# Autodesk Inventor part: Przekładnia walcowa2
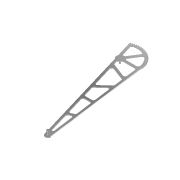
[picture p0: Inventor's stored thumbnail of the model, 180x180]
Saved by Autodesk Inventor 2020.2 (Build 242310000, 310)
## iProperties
Manager: www.cadconsulting.pl
Company: Fabian Stasiak CAD Consulting
CustomPartVersion: 1
Created: 2014-10
Part Number: Przekładnia walcowa2
Material: Steel
Document SubType Name: Modeling
Designer: F.Stasiak
Categories: <?xml version="1.0" encoding="UTF-16"?> <MemberInstance><Categories><FamilyTemplate><FamilyTemplateParameter ValueType="xs:double" Id="1" ObjectReferenceKey="da
Density: 7.85 g/cm^3
Appearance: Chrom - polerowany
Mass: 1025.76 g
Surface Area: 707.949 cm^2
Volume: 130.67 cm^3
Catalog Web Link: www.expertbooks.pl
Author: F.Stasiak
Subject: Zbiór ćwiczeń. Autodesk Inventor 2020. Kurs Professional
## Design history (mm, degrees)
sketch "Sketch1"
  geometry: C1 r 112.125 at (0, 0)
  constraints: 1 centre point
  dimensions: "d0" = 224.25 diameter of C1 (= da_da)
extrude "Extrusion1" new body sketch "Sketch1" distance "d1" = 5 (= da_b); taper "d2" = 0 deg
workplane "Work Plane2"
sketch "Sketch2"
  geometry: C1 r 112.125 at (0, 0) reference; C2 r 109.255 at (0, 0)
  constraints: 1 centre point, 1 coincident
  dimensions: "d3" = 218.51064 diameter of C2 (= da_dw)
feature "Średnica podziałowa" sketch "Sketch2" dims "d4" = 10, "d5" = 0
workplane "Work Plane8"
workplane "Work Plane9"
feature "Przekładnia walcowa" dims "da_b" = 5, "da_d" = 217.25, "da_aw" = 130, "da_da" = 224.25, "da_df" = 211.9072, "da_dw" = 218.51064, angle "da_beta" = 0 deg, "da_lefttooth" = 0, "da_righttooth" = 0
sketch "Szkic8"
  geometry: C1 r 8 at (0, 0); 1 further point
  constraints: 1 centre point, 1 coincident
  dimensions: "d66" = 16 diameter of C1
extrude "Wyciągnięcie proste6" join sketch "Szkic8" distance "d67" = 2; taper "d68" = 0 deg
sketch "Szkic9"
  geometry: C1 r 4 at (0, 0); 1 further point
  constraints: 1 centre point, 1 coincident
  dimensions: "d69" = 8 diameter of C1
extrude "Wyciągnięcie proste7" join sketch "Szkic9" distance "d70" = 20; taper "d71" = 0 deg
sketch "Szkic10"
  geometry: C1 r 8 at (0, 0); 1 further point
  constraints: 1 centre point, 1 coincident
  dimensions: "d72" = 16 diameter of C1
extrude "Wyciągnięcie proste8" join sketch "Szkic10" distance "d73" = 2; taper "d74" = 0 deg
sketch "Szkic11"
  geometry: L1 (125, 0)-(15, 0); L2 (-6.339, 13.595)-(-52.827, 113.288); L3 (15, 0)-(0, 0); L4 (0, 0)-(-6.339, 13.595); A1 r 125 centre (0, 0) between (-52.827, 113.288) and (125, 0); A2 r 15 centre (0, 0) between (-6.339, 13.595) and (15, 0); 1 further point
  constraints: 8 end point, 4 point on circle, 2 centre point, 2 coincident, 2 horizontal, 1 collinear
  dimensions: "d75" = 250 diameter of A1; "d76" = 115 deg angle of L2 L1; "d77" = 30 diameter of A2
extrude "Wyciągnięcie proste9" cut sketch "Szkic11" extent not by distance; stored distance "d80" = 2; taper "d81" = 0 deg
sketch "Szkic12"
  geometry: L1 (15, 0)-(109.382, 0) reference; L2 (-44.778, 96.027)-(-6.339, 13.595) reference; L3 (109, 4.23)-(185.868, -572.965); L4 (156.622, -579.222)-(-14.378, -4.276); L5 (-44.778, 96.027)-(-14.378, -4.276); L6 (109, 4.23)-(-44.778, 96.027); A1 r 6 centre (170.999, -574.946) between (165.029, -575.537) and (176.97, -574.354); A2 r 15 centre (170.999, -574.946) between (185.868, -572.965) and (156.622, -579.222); A3 r 36.765 centre (95.445, 38.404) between (105.906, 3.16) and (111.987, 5.571) reference; A4 r 15 centre (0, 0) between (-6.339, 13.595) and (15, 0) reference; A5 r 105.954 centre (0, 0) between (105.948, 1.053) and (105.906, 3.16) reference; 1 further point
  constraints: 8 end point, 6 point on circle, 3 tangent, 2 centre point, 1 coincident
  dimensions: "d82" = 30 diameter of A2
extrude "Wyciągnięcie proste10" join sketch "Szkic12" distance "d83" = 5; taper "d84" = 0 deg
sketch "Szkic13"
  geometry: C1 r 6 at (170.999, -574.946); A1 r 15 centre (170.999, -574.946) between (156.622, -579.222) and (185.868, -572.965) reference; 1 further point
  constraints: 1 centre point, 1 coincident
  dimensions: "d85" = 12 diameter of C1
extrude "Wyciągnięcie proste11" join sketch "Szkic13" distance "d86" = 25; taper "d87" = 0 deg
sketch "Szkic14"
  geometry: L1 (-14.378, -4.276)-(156.622, -579.222) reference; L2 (185.868, -572.965)-(109, 4.23) reference; L3 (122.376, -421.985)-(151.909, -408.868); L4 (150.258, -396.471)-(118.927, -410.387); L5 (136.695, -294.632)-(84.499, -294.632); L6 (135.097, -282.632)-(80.93, -282.632); L7 (119.47, -165.286)-(61.685, -217.925); L8 (117.542, -150.809)-(57.886, -205.153); L9 (110.37, -96.96)-(14.913, -60.666); L10 (10.608, -46.191)-(108.569, -83.437); L11 (56.231, 78.553)-(15.206, 12.991); L12 (46.058, 84.918)-(5.042, 19.371); L13 (-4.465, 4.488)-(-5.327, 3.111); L14 (51.244, 81.894)-(10.608, 16.955); L15 (19.096, -6.001)-(98.257, -6.001); L16 (19.079, 5.999)-(96.659, 5.999); L17 (0, 0)-(4, 0); L18 (20, 0)-(97.458, 0); L19 (-30.402, 91.696)-(-8.517, 18.114); L20 (-4.465, 4.488)-(-2.121, -3.391); A1 r 96.605 centre (0, 0) between (95.759, 12.753) and (-30.402, 91.696); A2 r 6 centre (162.981, -537.462) between (157.23, -539.173) and (168.929, -536.67); A3 r 4 centre (0, 0) between (4, 0) and (-2.121, -3.391) reference; A4 r 20 centre (0, 0) between (19.079, 5.999) and (15.206, 12.991); A5 r 20.017 centre (0, 0) between (5.042, 19.371) and (19.096, -6.001); 3 further points
  constraints: 36 end point, 15 point on circle, 13 parallel, 4 centre point, 3 horizontal, 2 tangent, 1 coincident, 1 concentric, 30 other
  dimensions: "d93" = 12 dimension on L2 (= d92); "d94" = 6 radius of A2; "d96" = 12 distance between parallel lines of L4 L3 (= d92); "d97" = 12 distance between parallel lines of L6 L5 (= d92); "d98" = 12 distance between parallel lines of L8 L7 (= d92); "d99" = 12 distance between parallel lines of L10 L9 (= d92); "d102" = 12 distance between parallel lines of L12 L11; "d104" = 12 distance between parallel lines of L16 L15; "d113" = 12 dimension on L1
extrude "Wyciągnięcie proste12" cut sketch "Szkic14" extent not by distance; stored distance "d105" = 25; taper "d106" = 0 deg
fillet "Zaokrąglenie2" dims "d107" = 10, "d108" = 10
sketch "Szkic15"
  geometry: C1 r 20 at (0, 0); 1 further point
  constraints: 1 centre point, 1 coincident
  dimensions: "d109" = 40 diameter of C1
extrude "Wyciągnięcie proste13" join sketch "Szkic15" distance "d110" = 5; taper "d111" = 0 deg
fillet "Zaokrąglenie3" dims "d112" = 10
body "Solid1"
body "Srf1"
other parameters: "d17" = 0, "d34" = 0.39767 (computed from da_z), "d39" = 0, "d41" = 0, "d47" = 0, "d48" = 0, "d92" = 12, "d100" = 6, "d101" = 6, "d103" = 6
